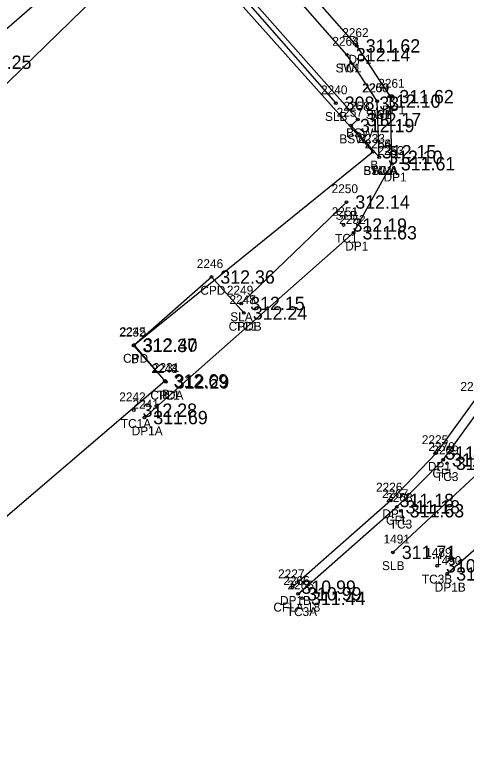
# Model space of a CAD drawing. Extents: x 1970076 to 1971136, y 803126 to 804215.
# Drawn here: x 1970347 to 1970397.9, y 803647.8 to 803730.6 of the extents above; entities that cross this region are included whole.
import ezdxf

# ---------------------------------------------------------------- set-up
doc = ezdxf.new("R2010")
doc.units = 0
for name, color, linetype in [('RD_EX_Bldg', 7, 'Continuous'), ('RD_EX_Bldg_txCode', 7, 'Continuous'), ('RD_EX_Conc', 7, 'Continuous'), ('RD_EX_Conc_txCode', 7, 'Continuous'), ('RD_EX_Driveway', 7, 'Continuous'), ('RD_EX_Driveway_txCode', 7, 'Continuous'), ('RD_EX_TX_Bldg_ELEV', 7, 'Continuous'), ('RD_EX_TX_Conc_ELEV', 7, 'Continuous'), ('RD_EX_TX_Driveway_ELEV', 7, 'Continuous'), ('RD_EX_TX_VEG_ELEV', 7, 'Continuous'), ('RD_EX_VEG', 7, 'Continuous'), ('RD_EX_VEG_txCode', 7, 'Continuous'), ('RD_SMD_Locator', 7, 'Continuous')]:
    doc.layers.add(name, color=color, linetype=linetype)

msp = doc.modelspace()

# ---------------------------------------------------------------- linework, layer by layer
at = {"layer": 'RD_EX_Bldg'}
msp.add_lwpolyline([(1970316.239, 803648.649), (1970363.887, 803689.383), (1970360.372, 803693.374), (1970387.334, 803715.199), (1970364.462, 803740.807), (1970337.816, 803714.899), (1970333.809, 803719.759), (1970289.788, 803679.246), (1970316.239, 803648.649)], dxfattribs=at)
at = {"layer": 'RD_EX_Conc'}
for points in [[(1970388.043, 803714.574), (1970387.812, 803720.9), (1970384.41, 803726.133), (1970362.198, 803751.392), (1970350.072, 803740.463), (1970336.455, 803728.473)], [(1970388.043, 803714.574), (1970384.866, 803718.144), (1970385.631, 803718.829), (1970368.137, 803738.615), (1970367.294, 803737.93), (1970364.409, 803741.02), (1970364.338, 803740.936), (1970361.218, 803738.424), (1970359.252, 803740.53), (1970341.72, 803725.277)], [(1970378.91, 803665.388), (1970390.009, 803675.178), (1970395.241, 803680.476), (1970399.794, 803686.756), (1970402.816, 803692.555), (1970405.342, 803699.423), (1970406.952, 803705.695), (1970409.991, 803712.539), (1970415.481, 803718.584), (1970420.848, 803722.328)], [(1970364.002, 803689.27), (1970360.431, 803693.426), (1970369.138, 803701.087), (1970372.797, 803697.031)]]:
    msp.add_lwpolyline(points, dxfattribs=at)
at = {"layer": 'RD_EX_Driveway'}
for points in [[(1970361.584, 803685.25), (1970385.155, 803706.07), (1970389.475, 803713.845), (1970389.303, 803721.405), (1970385.523, 803727.117), (1970356.232, 803760.398), (1970349.717, 803763.304), (1970344.215, 803762.632), (1970339.473, 803759.052), (1970338.114, 803753.777), (1970339.901, 803749.792), (1970347.988, 803740.685), (1970335.512, 803729.688)], [(1970424.723, 803724.099), (1970424.286, 803723.788), (1970419.367, 803723.185), (1970414, 803718.301), (1970409.058, 803712.485), (1970406.065, 803705.927), (1970404.327, 803699.669), (1970401.865, 803692.891), (1970398.82, 803687.26), (1970394.468, 803681.254), (1970389.336, 803675.913), (1970378.274, 803666.142)], [(1970511.893, 803542.412), (1970514.792, 803545.038), (1970514.012, 803573.46), (1970523.859, 803581.554), (1970466.06, 803647.507), (1970457.368, 803639.418), (1970456.639, 803639.958), (1970456.168, 803640.482), (1970453.444, 803643.559), (1970453.189, 803643.898), (1970452.573, 803644.606), (1970462.065, 803653.541), (1970470.49, 803657.022), (1970478.911, 803655.171), (1970478.911, 803655.171), (1970452.137, 803685.907), (1970452.137, 803685.907), (1970451.191, 803676.836), (1970447.704, 803671.466), (1970440.833, 803665.684), (1970436.405, 803664.894), (1970405.792, 803676.487), (1970395.71, 803667.638)]]:
    msp.add_lwpolyline(points, dxfattribs=at)
at = {"layer": 'RD_EX_VEG'}
for p, q in [((1970369.634, 803736.106), (1970383.155, 803720.666)), ((1970372.503, 803698.107), (1970384.344, 803709.534)), ((1970428.809, 803706.649), (1970389.584, 803670.063))]:
    msp.add_line(p, q, dxfattribs=at)
at = {"layer": 'RD_SMD_Locator'}
for centre in [(1970385.523, 803727.117), (1970384.41, 803726.133), (1970384.41, 803726.133), (1970387.812, 803720.9), (1970387.812, 803720.9), (1970389.303, 803721.405), (1970383.155, 803720.666), (1970385.631, 803718.829), (1970384.866, 803718.144), (1970387.334, 803715.199), (1970388.043, 803714.574), (1970388.043, 803714.574), (1970388.043, 803714.574), (1970389.475, 803713.845), (1970384.344, 803709.534), (1970384.031, 803706.942), (1970385.155, 803706.07), (1970369.138, 803701.087), (1970372.503, 803698.107), (1970372.797, 803697.031), (1970372.797, 803697.031), (1970360.431, 803693.426), (1970360.372, 803693.374), (1970363.887, 803689.383), (1970364.002, 803689.27), (1970364.002, 803689.27), (1970360.379, 803686.078), (1970361.584, 803685.25), (1970394.468, 803681.254), (1970395.241, 803680.476), (1970395.677, 803680.095), (1970389.336, 803675.913), (1970390.009, 803675.178), (1970390.471, 803674.748), (1970389.584, 803670.063), (1970394.564, 803668.55), (1970395.71, 803667.638), (1970378.274, 803666.142), (1970378.91, 803665.388), (1970379.353, 803664.884)]:
    msp.add_circle(centre, 0.15, dxfattribs=at)

# ---------------------------------------------------------------- texts
at = {"layer": 'RD_EX_Bldg_txCode'}
for s, p in [('2233', (1970385.704, 803716.199)), ('B', (1970387.027, 803713.199)), ('2232', (1970358.742, 803694.374)), ('B', (1970360.065, 803691.374)), ('2231', (1970362.541, 803690.383)), ('B', (1970363.58, 803687.383))]:
    msp.add_text(s, height=1, dxfattribs=at).set_placement(p)
at = {"layer": 'RD_EX_Conc_txCode'}
for s, p in [('2263', (1970382.757, 803727.133)), ('2264', (1970382.757, 803727.133)), ('SWL', (1970383.119, 803724.133)), ('TC1', (1970383.449, 803724.133)), ('2260', (1970386.119, 803721.9)), ('2259', (1970386.182, 803721.9)), ('2257', (1970383.236, 803719.144)), ('2258', (1970384.001, 803719.829)), ('SWL', (1970386.521, 803718.9)), ('TC1', (1970386.851, 803718.9)), ('BSW', (1970384.316, 803716.829)), ('BSW', (1970383.551, 803716.144)), ('2256', (1970386.39, 803715.574)), ('2254', (1970386.413, 803715.574)), ('2255', (1970386.413, 803715.574)), ('SWLA', (1970386.264, 803712.574)), ('BSWA', (1970386.24, 803712.574)), ('TC1', (1970387.082, 803712.574)), ('2251', (1970382.685, 803707.942)), ('TC1', (1970383.071, 803704.942)), ('2246', (1970367.484, 803702.087)), ('CPD', (1970367.886, 803699.087)), ('2247', (1970371.167, 803698.031)), ('2248', (1970371.167, 803698.031)), ('CPDB', (1970371.072, 803695.031)), ('TC1', (1970371.836, 803695.031)), ('2245', (1970358.801, 803694.426)), ('CPD', (1970359.179, 803691.426)), ('2243', (1970362.372, 803690.27)), ('2244', (1970362.372, 803690.27)), ('2242', (1970358.749, 803687.078)), ('CPDA', (1970362.262, 803687.27)), ('TC1', (1970363.041, 803687.27)), ('TC1A', (1970358.93, 803684.078)), ('2270', (1970393.572, 803681.476)), ('2269', (1970394.024, 803681.095)), ('CFL', (1970394.036, 803678.476)), ('TC3', (1970394.433, 803678.095)), ('2267', (1970388.355, 803676.178)), ('2268', (1970388.818, 803675.748)), ('CFL', (1970388.804, 803673.178)), ('TC3', (1970389.227, 803672.748)), ('1489', (1970393.218, 803669.55)), ('2266', (1970377.232, 803666.388)), ('TC3B', (1970392.848, 803666.55)), ('2265', (1970377.7, 803665.884)), ('CFLA 18', (1970376.114, 803663.388)), ('TC3A', (1970377.621, 803662.884))]:
    msp.add_text(s, height=1, dxfattribs=at).set_placement(p)
at = {"layer": 'RD_EX_Driveway_txCode'}
for s, p in [('2262', (1970383.869, 803728.117)), ('DP1', (1970384.578, 803725.117)), ('2261', (1970387.933, 803722.405)), ('DP1', (1970388.358, 803719.405)), ('2253', (1970387.845, 803714.845)), ('DP1', (1970388.53, 803711.845)), ('2252', (1970383.525, 803707.07)), ('DP1', (1970384.211, 803704.07)), ('2224', (1970397.19, 803688.26)), ('2241', (1970360.238, 803686.25)), ('DP1A', (1970360.151, 803683.25)), ('2225', (1970392.838, 803682.254)), ('DP1', (1970393.523, 803679.254)), ('2226', (1970387.682, 803676.913)), ('DP1', (1970388.391, 803673.913)), ('1490', (1970394.324, 803668.638)), ('2227', (1970376.644, 803667.142)), ('DP1B', (1970394.292, 803665.638)), ('DP1B', (1970376.857, 803664.142))]:
    msp.add_text(s, height=1, dxfattribs=at).set_placement(p)
at = {"layer": 'RD_EX_TX_Bldg_ELEV'}
for s, p in [('312.15', (1970388.334, 803714.449)), ('312.37', (1970361.372, 803692.624)), ('312.69', (1970364.887, 803688.633))]:
    msp.add_text(s, height=1.5, dxfattribs=at).set_placement(p)
at = {"layer": 'RD_EX_TX_Conc_ELEV'}
for s, p in [('312.14', (1970385.41, 803725.383)), ('312.14', (1970385.41, 803725.383)), ('312.25', (1970342.72, 803724.527)), ('312.10', (1970388.812, 803720.15)), ('312.10', (1970388.812, 803720.15)), ('312.17', (1970386.631, 803718.079)), ('312.19', (1970385.866, 803717.394)), ('312.10', (1970389.043, 803713.824)), ('312.10', (1970389.043, 803713.824)), ('312.10', (1970389.043, 803713.824)), ('312.19', (1970385.031, 803706.192)), ('312.36', (1970370.138, 803700.337)), ('312.24', (1970373.797, 803696.281)), ('312.24', (1970373.797, 803696.281)), ('312.40', (1970361.431, 803692.676)), ('312.29', (1970365.002, 803688.52)), ('312.29', (1970365.002, 803688.52)), ('312.28', (1970361.379, 803685.328)), ('311.17', (1970396.241, 803679.726)), ('311.62', (1970396.677, 803679.345)), ('311.18', (1970391.009, 803674.428)), ('311.63', (1970391.471, 803673.998)), ('310.68', (1970395.564, 803667.8)), ('310.99', (1970379.91, 803664.638)), ('311.44', (1970380.353, 803664.134))]:
    msp.add_text(s, height=1.5, dxfattribs=at).set_placement(p)
at = {"layer": 'RD_EX_TX_Driveway_ELEV'}
for s, p in [('311.62', (1970386.523, 803726.367)), ('311.62', (1970390.303, 803720.655)), ('311.61', (1970390.475, 803713.095)), ('311.63', (1970386.155, 803705.32)), ('311.69', (1970362.584, 803684.5)), ('311.19', (1970395.468, 803680.504)), ('311.18', (1970390.336, 803675.163)), ('310.31', (1970396.71, 803666.888)), ('310.99', (1970379.274, 803665.392))]:
    msp.add_text(s, height=1.5, dxfattribs=at).set_placement(p)
at = {"layer": 'RD_EX_TX_VEG_ELEV'}
for s, p in [('308.33', (1970384.155, 803719.916)), ('312.14', (1970385.344, 803708.784)), ('312.15', (1970373.503, 803697.357)), ('311.71', (1970390.584, 803669.313))]:
    msp.add_text(s, height=1.5, dxfattribs=at).set_placement(p)
at = {"layer": 'RD_EX_VEG_txCode'}
for s, p in [('2240', (1970381.486, 803721.666)), ('SLB', (1970381.927, 803718.666)), ('2250', (1970382.675, 803710.534)), ('SLB', (1970383.116, 803707.534)), ('2249', (1970370.873, 803699.107)), ('SLA', (1970371.259, 803696.107)), ('1491', (1970388.521, 803671.063)), ('SLB', (1970388.356, 803668.063))]:
    msp.add_text(s, height=1, dxfattribs=at).set_placement(p)

doc.saveas('drawing.dxf')
